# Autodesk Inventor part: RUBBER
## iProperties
Author: GJOHNST2
Created: 2001-11
Part Number: RUBBER
Document SubType Name: Modeling
Designer: GJOHNST2
Control State: 0
Master: False
Checked Out: False
PropertySet Name: Design Tracking Control
Shininess: 64.0
Angle Display Precision: 2
Document Length Units: 11272
Document Angle Units: 11286
Document Time Units: 11279
Document Mass Units: 11290
Document Length Units Precision: 3
Document Angle Units Precision: 2
Compacted: True
PropertySet Name: _Private Model Information
Density: 0.0
Volumn: 0.0
Area: 0.0
PropertySet Name: Model Information
